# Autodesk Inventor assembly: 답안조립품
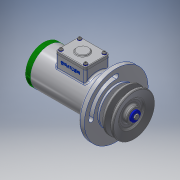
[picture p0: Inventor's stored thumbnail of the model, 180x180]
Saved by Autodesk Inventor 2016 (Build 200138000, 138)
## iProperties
Created: 2017-05
Part Number: 답안조립품
Material: 일반
Document SubType Name: Assembly
Designer: USER
Author: USER
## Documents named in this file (20)
- C:\Users\USER\Desktop\470508V1014\답안조립품.iam
- C:\Users\USER\Desktop\470508V1014\본체.ipt
- C:\Users\USER\Desktop\470508V1014\V-벨트풀리.ipt
- C:\Users\USER\Desktop\470508V1014\너트 M10.ipt
- C:\Users\USER\Desktop\470508V1014\멈춤링 15 x 1.ipt
- C:\Users\USER\Desktop\470508V1014\멈춤링 35x1.6.ipt
- C:\Users\USER\Desktop\470508V1014\베어링 15 x 35 x 11.ipt
- C:\Users\USER\Desktop\470508V1014\볼트 M4 x 10.ipt
- C:\Users\USER\Desktop\470508V1014\부시1.ipt
- C:\Users\USER\Desktop\470508V1014\부시2.ipt
- C:\Users\USER\Desktop\470508V1014\사이드 커버.ipt
- 사이드 커버.ipt
- C:\Users\USER\Desktop\470508V1014\십자볼트 M3 x 10.ipt
- C:\Users\USER\Desktop\470508V1014\오일 실 15 25 7.ipt
- C:\Users\USER\Desktop\470508V1014\와셔 3x6.ipt
- C:\Users\USER\Desktop\470508V1014\와셔 4x16.ipt
- C:\Users\USER\Desktop\470508V1014\와셔 10x21.ipt
- C:\Users\USER\Desktop\470508V1014\축.ipt
- C:\Users\USER\Desktop\470508V1014\키 4 x 4 x 18.ipt
- C:\Users\USER\Desktop\470508V1014\탑 커버.ipt
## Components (2 placed, 2 different names)
1. V-벨트풀리:1
2. ISO 4017 M4 x 10:1
## Named parameters: d39_d37 = 0, d40_d38 = 0, d41_d37 = 0, d42_d38 = 0, d43_d37 = 0, d44_d38 = 0
